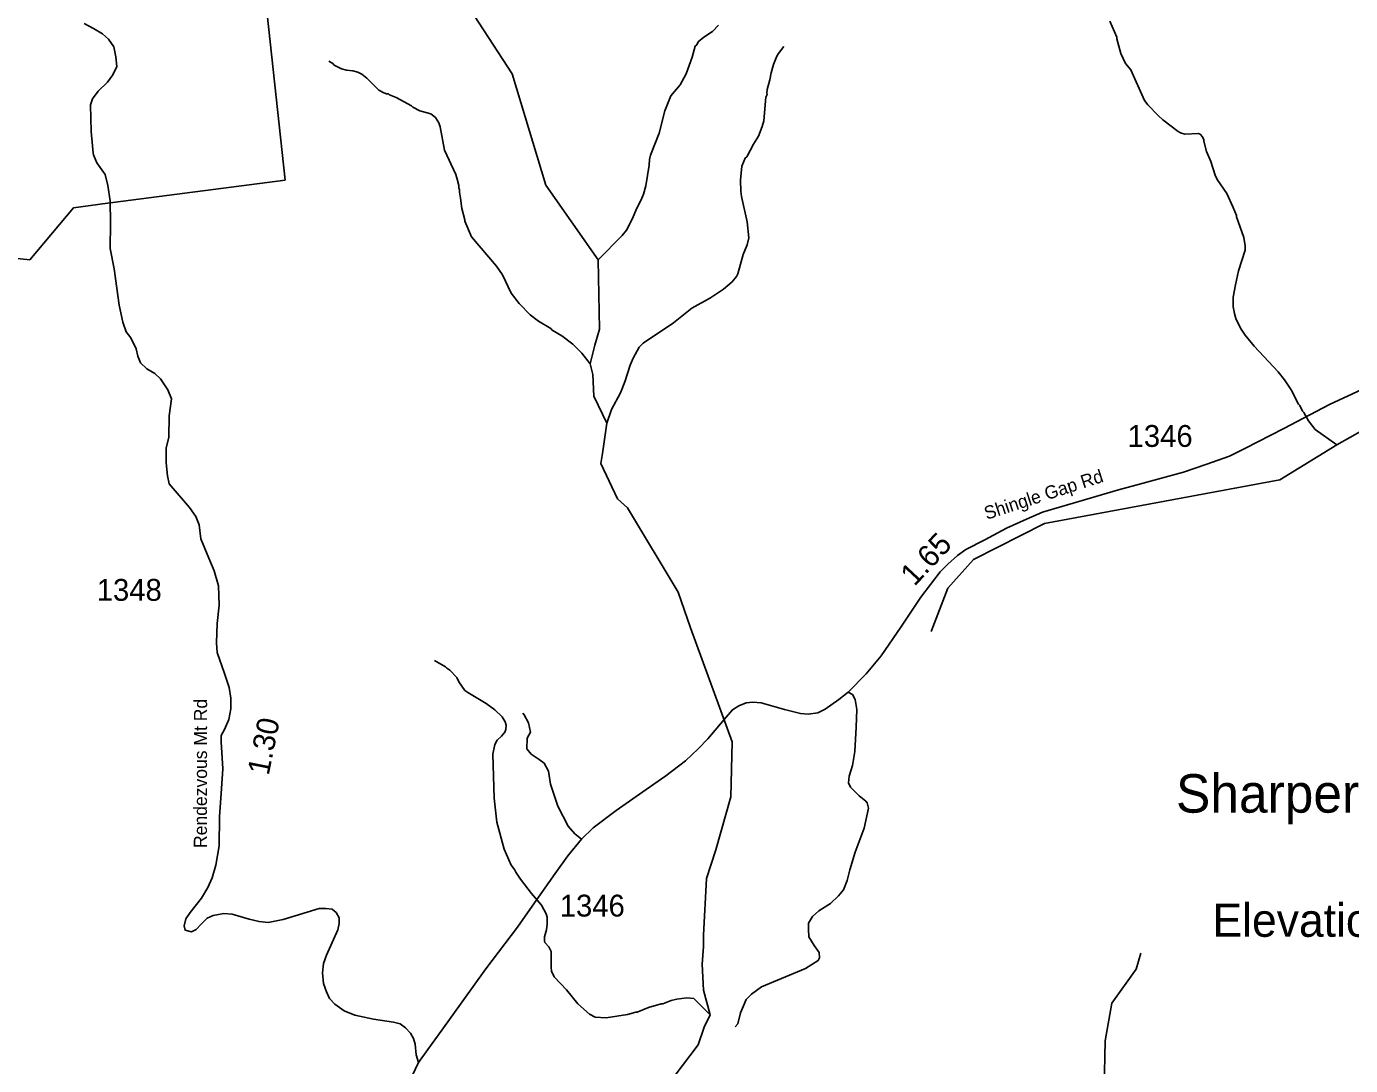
# Model space of a CAD drawing. Extents: x 1248224 to 1454986, y 825081 to 985870.
# Drawn here: x 1323531 to 1331099, y 901499 to 907441 of the extents above; entities that cross this region are included whole.
import ezdxf

# ---------------------------------------------------------------- set-up
doc = ezdxf.new("R2010")
doc.units = 0
for name, color, linetype in [('Exist Boundary Land Use Forest State Division NC Forest Resources', 7, 'Continuous'), ('Exist Geographical Mountain Summit Elevation Number Label', 7, 'Continuous'), ('Exist Geographical Mountain Summit Label', 7, 'Continuous'), ('Exist Hydrographic Creek Single Shore', 7, 'Continuous'), ('Exist Hydrographic Misc Water Feature', 7, 'Continuous'), ('Exist Road Non-System Type 51', 7, 'Continuous'), ('Exist Road Secondary Mileage Hundredths English Label', 7, 'Continuous'), ('Exist Road Secondary Type 41 Attributed', 7, 'Continuous'), ('Exist Road Secondary Type 51 Attributed', 7, 'Continuous'), ('Exist Road Secondary Type 51 Label', 7, 'Continuous'), ('Exist Road Secondary Type 51 Number Label', 7, 'Continuous')]:
    doc.layers.add(name, color=color, linetype=linetype)

msp = doc.modelspace()

# ---------------------------------------------------------------- linework, layer by layer
at = {"layer": 'Exist Boundary Land Use Forest State Division NC Forest Resources'}
msp.add_lwpolyline([(1324906, 907512.6), (1325009, 906562.9), (1324025, 906433.9), (1323995, 906429.9), (1323798.9, 906404), (1323550, 906107.6), (1321998.5, 906270.6), (1321929.4, 904952.5), (1321832.6, 904809), (1321268.9, 904603.8), (1321214.3, 904295.1), (1321305.6, 904044.6), (1320617, 903827.5), (1320574.8, 904227.1), (1320380.9, 904203.6), (1320374.2, 904688.2), (1319448, 904573.1), (1319231.6, 904771.2), (1319273, 905485.9), (1319066.4, 905473.3), (1318700.4, 905123.8)], dxfattribs=at)
at = {"layer": 'Exist Hydrographic Creek Single Shore'}
for points in [[(1328701.2, 903981), (1328798.2, 904228.5), (1328944.2, 904393.1), (1329349.2, 904598.3), (1330694.1, 904848.7), (1331019.9, 905048.1), (1331467.3, 905301.1)], [(1327232.2, 901436.7), (1327370.2, 901617.8), (1327405.2, 901718.9), (1327438.4, 901788.1), (1327400, 901930.1), (1327392.4, 902079.7), (1327400, 902179.4), (1327401.2, 902244.2), (1327417.2, 902568.9), (1327471.2, 902732), (1327557, 903036.4), (1327564.8, 903350.5), (1327327, 904001.3), (1327255.2, 904207.1), (1326966.2, 904688.9), (1326909.2, 904739.2), (1326814.1, 904941.5), (1326822.7, 904998.7)], [(1329353.3, 900345.4), (1329360.2, 900402.7), (1329575.2, 900706.9), (1329637.3, 900840.2), (1329684.2, 901098.6), (1329697.2, 901640.1), (1329735.3, 901856), (1329873.3, 902050.2), (1329900.2, 902141.5)]]:
    msp.add_lwpolyline(points, dxfattribs=at)
at = {"layer": 'Exist Hydrographic Misc Water Feature'}
for points in [[(1326822.7, 904998.7), (1326848.6, 905172.4), (1326773.1, 905326.4), (1326767.2, 905450.8), (1326752.1, 905511.5), (1326779.2, 905618.4), (1326806.1, 905709.8), (1326798, 906106.1), (1326500.1, 906533.3), (1326307.1, 907170.8), (1326089, 907503.5), (1325845, 907767.7), (1325742, 907976.7), (1325735, 908042.4), (1325558.1, 908321.8), (1325440.1, 908616.3)], [(1327487.1, 907449.2), (1327452, 907412.2), (1327403, 907379.6), (1327370.3, 907352.6), (1327361.8, 907336.8), (1327353.6, 907329), (1327335.9, 907265.6), (1327301.1, 907170.6), (1327267.4, 907107.6), (1327213.6, 907045.1), (1327179.1, 906958.2), (1327147.5, 906831.2), (1327097.9, 906704.6), (1327091.2, 906680.9), (1327090.3, 906648.9), (1327071, 906529.4), (1327057.6, 906481.9), (1327044.8, 906450.3), (1327019.4, 906403), (1326993.6, 906339.8), (1326959.8, 906276.7), (1326935, 906245.4), (1326798, 906106.1)], [(1329722.7, 907472.5), (1329764.1, 907379.4), (1329763.9, 907371.4), (1329785.5, 907286.8), (1329811.9, 907230), (1329842.9, 907193.1), (1329922, 907018.9), (1329941.3, 906992.3), (1329999.6, 906932.7), (1330027, 906907.8), (1330113.1, 906841.4), (1330126.9, 906833), (1330152.8, 906826.2), (1330230.9, 906830), (1330238.8, 906825.7), (1330252.3, 906809.4), (1330259.8, 906793.1), (1330259.6, 906785.2), (1330276, 906726.7), (1330300.4, 906670), (1330326.1, 906591.4), (1330337.5, 906566.9), (1330391.2, 906485.4), (1330429.1, 906406.4), (1330447.7, 906359.8), (1330447.5, 906351.8), (1330488.2, 906234.8), (1330496.8, 906186.5), (1330496.2, 906162.5), (1330458.8, 906043.7), (1330440.6, 905964.2), (1330428.6, 905892.5), (1330429.1, 905838.6), (1330435.9, 905800.4), (1330443.2, 905772.2), (1330469.6, 905715.5), (1330496.5, 905676.6), (1330548.7, 905613.1), (1330684.7, 905465.3), (1330721.4, 905420.2), (1330759.8, 905363.1), (1330801.6, 905282), (1330809.3, 905273.7), (1330824.4, 905241.3), (1330832.2, 905233.1), (1330858.9, 905186.3), (1330897.5, 905137.2), (1331019.9, 905048.1)], [(1327859.8, 907326.5), (1327828.6, 907287.3), (1327820.2, 907271.6), (1327800.8, 907224.1), (1327787.5, 907176.6), (1327780.4, 907136.8), (1327764.8, 907081.2), (1327762.2, 907059.3), (1327764, 907053.2), (1327757.6, 907037.4), (1327745.8, 906901.8), (1327736.8, 906870.1), (1327715.3, 906814.8), (1327686, 906767.6), (1327648, 906696.7), (1327639.8, 906689), (1327620.4, 906641.5), (1327612.2, 906561.8), (1327614.4, 906499.8), (1327617.6, 906469.7), (1327649.5, 906324.8), (1327658.9, 906232.5), (1327649.8, 906192.8), (1327628.3, 906137.5), (1327597.1, 906026.4), (1327588.6, 906010.6), (1327563.8, 905981.3), (1327514.6, 905938.8), (1327441.2, 905888.9), (1327333.4, 905830.1), (1327229, 905747.2), (1327055.7, 905630.2), (1327033, 905606.8), (1326999.3, 905543.8), (1326982.2, 905504.4), (1326951.4, 905409.2), (1326925.7, 905346), (1326875, 905251.5), (1326848.6, 905172.4)], [(1325258.3, 907243.6), (1325281.9, 907229), (1325289.7, 907220.8), (1325331.1, 907199.5), (1325360.8, 907190.7), (1325396.8, 907187.6), (1325424.6, 907180.9), (1325448.3, 907168.2), (1325475.6, 907145.4), (1325545.8, 907077.4), (1325573.3, 907062.6), (1325589.1, 907056.1), (1325601.1, 907055.8), (1325605, 907049.6), (1325644.6, 907034.6), (1325731.3, 906988), (1325739, 906979.8), (1325778.5, 906958.7), (1325842.1, 906940.9), (1325869.4, 906920), (1325888.6, 906889.5), (1325896, 906867.4), (1325920.3, 906734.7), (1325984.4, 906594.8), (1325993.6, 906568.6), (1326002.6, 906532.3), (1326002.1, 906516.4), (1326005.9, 906508.3), (1326005.5, 906494.3), (1326012.6, 906460.1), (1326018.9, 906399.9), (1326037.1, 906335.4), (1326036.9, 906327.4), (1326074.4, 906238.4), (1326217.7, 906070.2), (1326252.4, 906021.3), (1326301.4, 905915.9), (1326347.7, 905856.5), (1326410, 905792.8), (1326456.9, 905755.5), (1326527.8, 905713.4), (1326535.5, 905705.2), (1326590.7, 905671.6), (1326653.4, 905623.8), (1326705.9, 905572.2), (1326752.1, 905511.5)], [(1325862.2, 903815.3), (1325925.1, 903779.4), (1325932.9, 903771.2), (1325950.6, 903760.7), (1325991.4, 903717.5), (1326002.7, 903693.1), (1326037.4, 903644.2), (1326053.1, 903631.7), (1326159.3, 903568.7), (1326208.4, 903533.3), (1326249.3, 903494.1), (1326266.5, 903465.6), (1326272, 903445.4), (1326271.2, 903421.5), (1326264.8, 903405.7), (1326246.1, 903382.3), (1326221.4, 903358.9), (1326208.8, 903335.3), (1326197.2, 903279.7), (1326204.1, 903027.5), (1326220.3, 902891.1), (1326261.9, 902736), (1326301.4, 902644.8), (1326320.8, 902620.3), (1326328.2, 902604.1), (1326355.2, 902565.4), (1326416.9, 902483.5), (1326475.1, 902415.9), (1326501.7, 902367.2), (1326507.1, 902347), (1326508, 902307), (1326503.1, 902275.1), (1326492, 902235.4), (1326491.3, 902211.5), (1326493.1, 902203.4), (1326516.4, 902178.7), (1326529.6, 902150.4), (1326529.1, 902062.5), (1326532.5, 902038.4), (1326547.5, 902006), (1326617.5, 901932), (1326683.3, 901852.1), (1326749.6, 901792.1), (1326781.2, 901775.3), (1326845.1, 901771.4), (1326965.6, 901790), (1327014, 901804.5), (1327022.1, 901804.3), (1327086.8, 901830.3), (1327159.5, 901852.3), (1327167.5, 901852.1), (1327216, 901870.6), (1327248.2, 901877.7), (1327304.5, 901886.1), (1327344.5, 901882.9), (1327438.4, 901788.1)]]:
    msp.add_lwpolyline(points, dxfattribs=at)
at = {"layer": 'Exist Road Non-System Type 51'}
for points in [[(1324048.1, 907212.6), (1324042, 907267.8), (1324029.7, 907324.6), (1323999, 907369.2), (1323965.3, 907398.3), (1323914.7, 907430.6), (1323861, 907458.2)], [(1323912.7, 906717), (1323908.9, 906757.9), (1323901.3, 906840.4), (1323896.7, 906992.4), (1323907.5, 907027.7), (1323941.2, 907070.7), (1323994.9, 907122.9), (1324025.1, 907165), (1324048.1, 907212.6)], [(1328227.5, 903635.1), (1328252.8, 903620.5), (1328267.9, 903592.8), (1328278, 903534.8), (1328273, 903434), (1328265.4, 903295.5), (1328252.8, 903214.8), (1328232.7, 903154.4), (1328230.2, 903116.6), (1328240.3, 903091.4), (1328290.6, 903041), (1328328.4, 903010.7), (1328335.9, 903000.7), (1328343.5, 902970.4), (1328318.3, 902857), (1328267.9, 902718.4), (1328237.7, 902617.7), (1328222.6, 902557.2), (1328200, 902504.3), (1328172.3, 902469), (1328126.9, 902426.2), (1328059, 902383.3), (1328023.9, 902351.7), (1328001.2, 902313.9), (1328001.2, 902278.7), (1328003.7, 902235.8), (1328034, 902185.4), (1328061.7, 902145.1), (1328064.2, 902114.9), (1328056.6, 902099.8), (1327983.6, 902054.4), (1327731.8, 901948.6), (1327674.2, 901906.5), (1327644, 901876.2), (1327628.9, 901841), (1327611.3, 901800.7), (1327596.1, 901737.7), (1327582.6, 901721)], [(1326703.2, 902793), (1326665.4, 902824.2), (1326627.6, 902867.1), (1326567.2, 902983), (1326526.9, 903109), (1326514.3, 903182), (1326489.1, 903227.4), (1326461.4, 903250.1), (1326416.1, 903280.3), (1326390.9, 903310.5), (1326393.4, 903371), (1326411.1, 903406.3), (1326401, 903459.2), (1326375.8, 903504.5), (1326368.4, 903514.1)]]:
    msp.add_lwpolyline(points, dxfattribs=at)
at = {"layer": 'Exist Road Secondary Type 41 Attributed'}
msp.add_lwpolyline([(1325771.1, 901516), (1325759, 901560.7), (1325752.9, 901620.6), (1325743.7, 901654.3), (1325725.3, 901685), (1325697.6, 901714.2), (1325667, 901737.2), (1325628.6, 901748), (1325515.1, 901763.3), (1325407.7, 901787.9), (1325346.3, 901812.5), (1325294.2, 901850.9), (1325263.5, 901883.1), (1325246.6, 901919.9), (1325228.2, 901969.1), (1325222.1, 902028.9), (1325228.2, 902082.7), (1325246.6, 902130.3), (1325311.1, 902275), (1325317.3, 902311.9), (1325317.3, 902344.1), (1325300.4, 902373.3), (1325277.4, 902393.3), (1325242.1, 902397.9), (1325203.8, 902396.3), (1324998.2, 902333.4), (1324912.3, 902318), (1324860.1, 902322.6), (1324803.4, 902336.5), (1324706.7, 902365.6), (1324659.9, 902368.7), (1324598.5, 902358), (1324563.2, 902341.1), (1324529.5, 902307.3), (1324500.3, 902276.6), (1324474.2, 902264.3), (1324437.4, 902273.5), (1324432.8, 902298.1), (1324442, 902338), (1324466.6, 902373.3), (1324531, 902456.2), (1324567.8, 902517.6), (1324592.4, 902572.9), (1324613.8, 902645.1), (1324632.1, 902754.6), (1324635.1, 902921.9), (1324645.9, 903083.1), (1324653.6, 903195.2), (1324644.4, 903350.9), (1324644.4, 903386.2), (1324662.8, 903420), (1324687.3, 903478.3), (1324699.6, 903539.7), (1324699.6, 903599.6), (1324690.4, 903661), (1324662.8, 903740.9), (1324621.4, 903860.9), (1324616.8, 903916.2), (1324621.4, 904026.7), (1324632.1, 904131.1), (1324629.1, 904241.7), (1324603, 904327.6), (1324573.8, 904399.8), (1324527.9, 904510.8), (1324517.2, 904590.7), (1324498.8, 904638.2), (1324463.5, 904690.4), (1324346.9, 904825.5), (1324337.7, 904871.6), (1324328.5, 904945.3), (1324330.1, 905031.6), (1324343.9, 905091.5), (1324347, 905214.3), (1324359.3, 905311), (1324339.3, 905363.2), (1324297.9, 905426.2), (1324264.2, 905456.9), (1324218.1, 905483), (1324182.8, 905518.3), (1324167.5, 905555.1), (1324158.3, 905598.1), (1324126.6, 905660.1), (1324100.5, 905695.4), (1324082.1, 905750.7), (1324060.6, 905847.4), (1324046.8, 905944.1), (1324033, 906056.2), (1324010.1, 906171.9), (1324011.6, 906316.2), (1324008.5, 906443.6), (1323996.3, 906531.1), (1323980.9, 906594.1), (1323933.4, 906661.6), (1323913.6, 906706.8), (1323912.7, 906717)], dxfattribs=at)
at = {"layer": 'Exist Road Secondary Type 51 Attributed'}
for points in [[(1331163.8, 905365.2), (1330978.4, 905278.5), (1330716.9, 905141.8), (1330494.5, 905028.4), (1330406.4, 904983.9), (1330271.2, 904935.9), (1330144.8, 904892.3), (1329871.1, 904818.4), (1329773.7, 904790.8), (1329513.6, 904715.2), (1329337.8, 904662.9), (1329246.3, 904623.6), (1329132.9, 904572.7), (1329008.5, 904506.3), (1328899.5, 904449.6), (1328853, 904416.2), (1328796.4, 904366.7), (1328754.2, 904321.6), (1328642.7, 904178.4), (1328529.4, 904006.8), (1328416.4, 903843), (1328330.7, 903739.8), (1328227.5, 903635.1), (1328174.4, 903591.6), (1328095.9, 903536.4), (1328053.8, 903516), (1327998.6, 903508.7), (1327955, 903513.1), (1327863.5, 903534.9), (1327731.2, 903572.7), (1327683.3, 903577.1), (1327644, 903572.7), (1327601.9, 903556.7), (1327565.6, 903533.4), (1327517.9, 903477.3), (1327426.4, 903366.8), (1327369.7, 903310.1), (1327297, 903241.8), (1327185.6, 903156.5), (1327072.3, 903078), (1326900.8, 902957.3), (1326770.1, 902858.4), (1326703.2, 902793), (1326624.9, 902698.5), (1326552.3, 902596.7), (1326421.5, 902410.6), (1326337.2, 902291.3), (1326157, 902052.9), (1326020.5, 901863.8), (1325904.2, 901701), (1325825.8, 901590.4), (1325771.1, 901516)], [(1325771.1, 901516), (1325734.5, 901436.3), (1325714.3, 901359.2), (1325689.8, 901260)]]:
    msp.add_lwpolyline(points, dxfattribs=at)

# ---------------------------------------------------------------- texts
at = {"layer": 'Exist Geographical Mountain Summit Elevation Number Label'}
msp.add_text('Elevation 1895', height=190, dxfattribs=at).set_placement((1330310, 902235.3))
at = {"layer": 'Exist Geographical Mountain Summit Label'}
msp.add_text('Sharper Mountain', height=220, dxfattribs=at).set_placement((1330101.5, 902945.2))
at = {"layer": 'Exist Road Secondary Mileage Hundredths English Label'}
for s, rotation, p in [('1.65', 46.93203, (1328606.1, 904235.2)), ('1.30', 78.69831, (1324915.5, 903154.3))]:
    msp.add_text(s, height=125, rotation=rotation, dxfattribs=at).set_placement(p)
at = {"layer": 'Exist Road Secondary Type 51 Label'}
for s, rotation, p in [('Shingle Gap Rd', 18.04566, (1329019.4, 904619.5)), ('Rendezvous Mt Rd', 89.93027, (1324562.3, 902743.2))]:
    msp.add_text(s, height=75, rotation=rotation, dxfattribs=at).set_placement(p)
at = {"layer": 'Exist Road Secondary Type 51 Number Label'}
for s, p in [('1346', (1329824.8, 905037)), ('1348', (1323932.5, 904156.8)), ('1346', (1326579, 902351.1))]:
    msp.add_text(s, height=125, dxfattribs=at).set_placement(p)

doc.saveas('drawing.dxf')
